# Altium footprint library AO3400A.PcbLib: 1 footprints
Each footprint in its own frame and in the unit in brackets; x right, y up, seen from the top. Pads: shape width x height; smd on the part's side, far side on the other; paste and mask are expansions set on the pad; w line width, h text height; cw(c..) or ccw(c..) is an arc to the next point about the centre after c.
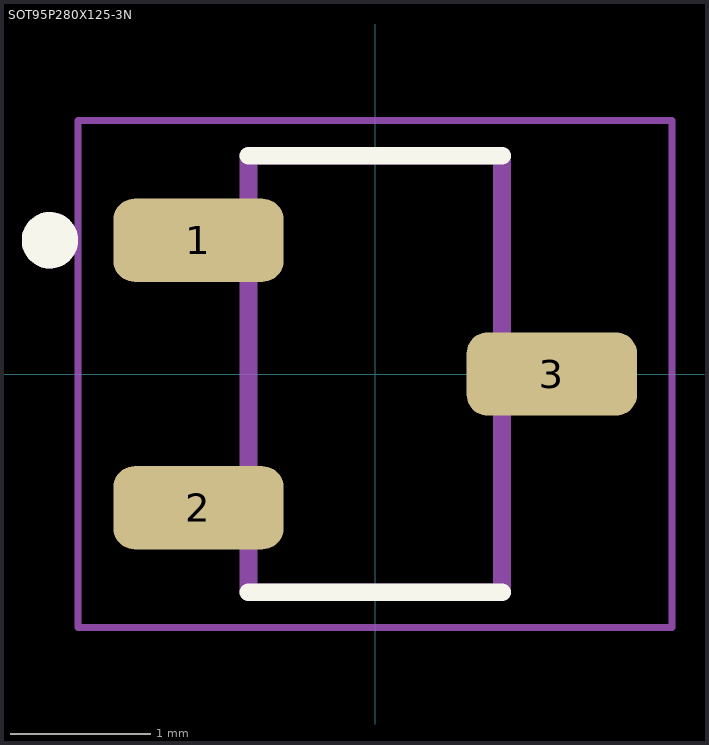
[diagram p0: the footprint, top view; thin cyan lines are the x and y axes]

## SOT95P280X125-3N [mm]
pads (3):
  rrect50% 1.21x0.59 smd: 1(-1.255,0.95) 2(-1.255,-0.95) 3(1.255,0)
Top Overlay:
  circle w0.2: c-2.31,0.95 r0.1
  lines w0.127: -0.9,-1.55 0.9,-1.55 ; -0.9,1.55 0.9,1.55
Assembly Top:
  circle w0.2: c-2.31,0.95 r0.1
  lines w0.127: -0.9,-1.55 -0.9,1.55 0.9,1.55 0.9,-1.55 -0.9,-1.55
Courtyard Top:
  lines w0.05: -2.11,-1.8 -2.11,1.8 2.11,1.8 2.11,-1.8 -2.11,-1.8
3D body "step_temp.STEP": height 1.25, standoff 0, extent -1.4,-1.45 1.4,1.45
